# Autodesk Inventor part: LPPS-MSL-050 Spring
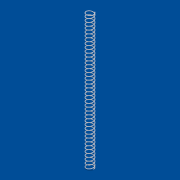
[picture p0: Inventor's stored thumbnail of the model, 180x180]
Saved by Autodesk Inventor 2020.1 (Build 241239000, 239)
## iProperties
Created: 2019-08
Part Number: LPPS-MSL-050 Spring
Material: Stainless Steel
Document SubType Name: Modeling
Designer: J. Nielson
Density: 8 g/cm^3
Appearance: Semi-Polished
Author: J. Nielson
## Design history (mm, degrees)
sketch "Sketch1"
  geometry: L1 (-2.5, 121.4)-(2.5, 121.4) reference; L2 (4, 48.746)-(-4, 48.746) reference; L3 (0, 121.4)-(0, 48.746); C1 r 0.14 at (1.905, 48.886); 1 further point
  constraints: 2 end point, 2 midpoint, 1 centre point, 1 tangent
  dimensions: "d0" = 72.654 distance of L3.start L3.end (derived); "d1" = 0.2794 diameter of C1; "d2" = 1.905 distance from line of L3 C1.centre
coil "Coil1" sketch "Sketch1" pitch "d3" = 25.4; turns "d5" = 40; dims "d4" = 72.3746 (= d0 - d1), "d6" = 0, angle "d7" = 30 deg, angle "d8" = 180 deg, "d9" = 30 deg, "d10" = 180 deg
sketch "Sketch2"
  geometry: L1 (-1.905, -73.166)-(-1.905, 96.794) reference; 5 further points
  constraints: 2 horizontal alignment
  node "Projected Loop1"
revolve "Revolution1" stored, may be unused: angle "d11" = 135 deg
revolve "Revolution2" stored, may be unused: angle "d12" = 135 deg
body "Solid1"
node "Reference1"
node "Reference2"
